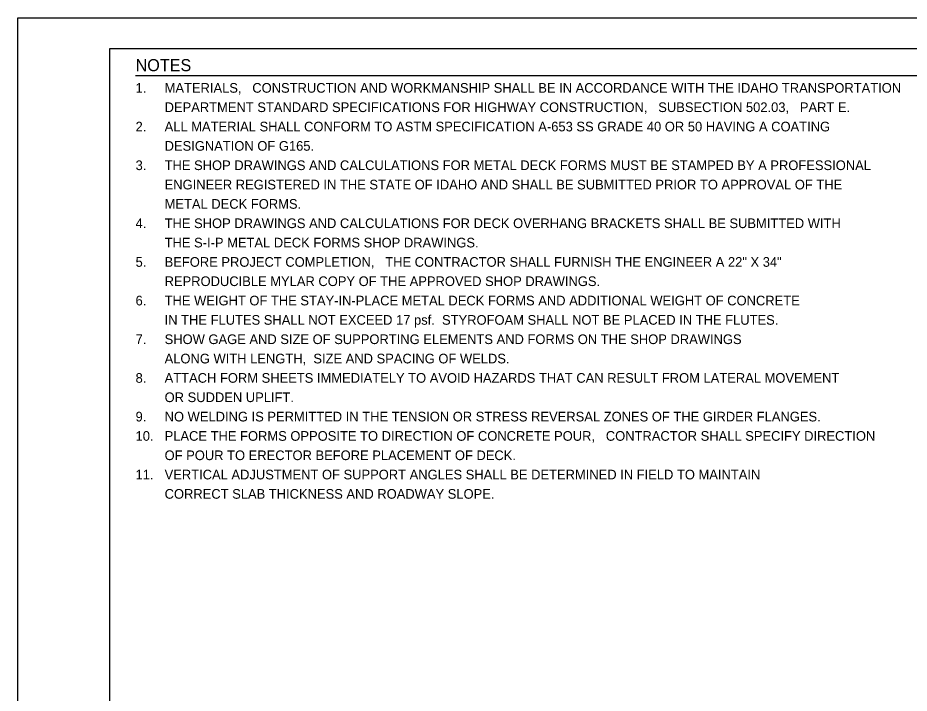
# Model space of a CAD drawing. Extents: x 0 to 34, y 0 to 23.5.
# Drawn here: x 0 to 14.51, y 11 to 22 of the extents above; entities that cross this region are included whole.
import ezdxf

# ---------------------------------------------------------------- set-up
doc = ezdxf.new("R2010")
doc.units = 0
for name, color, linetype in [('BORDER_ANNO_Cutsheet', 7, 'Continuous'), ('BRDG_ANNO_Anno-Sheet', 7, 'Continuous'), ('BRDG_ANNO_General-Notes', 7, 'Continuous')]:
    doc.layers.add(name, color=color, linetype=linetype)

msp = doc.modelspace()

# ---------------------------------------------------------------- linework, layer by layer
at = {"layer": 'BORDER_ANNO_Cutsheet'}
msp.add_lwpolyline([(0, 22), (34, 22), (34, 0), (0, 0)], close=True, dxfattribs=at)
at = {"layer": 'BRDG_ANNO_Anno-Sheet'}
msp.add_lwpolyline([(1.5, 21.5), (33.5, 21.5), (33.5, 0.5), (1.5, 0.5)], close=True, dxfattribs=at)
at = {"layer": 'BRDG_ANNO_General-Notes'}
msp.add_line((1.917, 21.061), (15.124, 21.061), dxfattribs=at)

# ---------------------------------------------------------------- texts
for s, height, p in [('NOTES', 0.1968, (1.917, 21.131)), ('1.', 0.1574, (1.917, 20.78)), ('MATERIALS,   CONSTRUCTION AND WORKMANSHIP SHALL BE IN ACCORDANCE WITH THE IDAHO TRANSPORTATION', 0.15746, (2.39, 20.78)), ('DEPARTMENT STANDARD SPECIFICATIONS FOR HIGHWAY CONSTRUCTION,   SUBSECTION 502.03,   PART E.', 0.15746, (2.39, 20.465)), ('2.', 0.1575, (1.917, 20.15)), ('ALL MATERIAL SHALL CONFORM TO ASTM SPECIFICATION A-653 SS GRADE 40 OR 50 HAVING A COATING', 0.15746, (2.39, 20.15)), ('DESIGNATION OF G165.', 0.15746, (2.39, 19.835)), ('3.', 0.1575, (1.917, 19.52)), ('THE SHOP DRAWINGS AND CALCULATIONS FOR METAL DECK FORMS MUST BE STAMPED BY A PROFESSIONAL', 0.15745, (2.39, 19.52)), ('ENGINEER REGISTERED IN THE STATE OF IDAHO AND SHALL BE SUBMITTED PRIOR TO APPROVAL OF THE', 0.15745, (2.39, 19.205)), ('METAL DECK FORMS.', 0.15745, (2.39, 18.89)), ('4.', 0.1575, (1.917, 18.575)), ('THE SHOP DRAWINGS AND CALCULATIONS FOR DECK OVERHANG BRACKETS SHALL BE SUBMITTED WITH', 0.15745, (2.39, 18.575)), ('THE S-I-P METAL DECK FORMS SHOP DRAWINGS.', 0.15745, (2.39, 18.26)), ('5.', 0.1575, (1.917, 17.945)), ('BEFORE PROJECT COMPLETION,   THE CONTRACTOR SHALL FURNISH THE ENGINEER A 22" X 34"', 0.15745, (2.39, 17.945)), ('REPRODUCIBLE MYLAR COPY OF THE APPROVED SHOP DRAWINGS.', 0.15745, (2.39, 17.631)), ('6.', 0.1575, (1.917, 17.316)), ('THE WEIGHT OF THE STAY-IN-PLACE METAL DECK FORMS AND ADDITIONAL WEIGHT OF CONCRETE', 0.15745, (2.39, 17.316)), ('IN THE FLUTES SHALL NOT EXCEED 17 psf.  STYROFOAM SHALL NOT BE PLACED IN THE FLUTES.', 0.15746, (2.39, 17.001)), ('7.', 0.1575, (1.917, 16.686)), ('SHOW GAGE AND SIZE OF SUPPORTING ELEMENTS AND FORMS ON THE SHOP DRAWINGS', 0.15745, (2.39, 16.686)), ('ALONG WITH LENGTH,  SIZE AND SPACING OF WELDS.', 0.15745, (2.39, 16.371)), ('8.', 0.1575, (1.917, 16.056)), ('ATTACH FORM SHEETS IMMEDIATELY TO AVOID HAZARDS THAT CAN RESULT FROM LATERAL MOVEMENT', 0.15745, (2.39, 16.056)), ('OR SUDDEN UPLIFT.', 0.15745, (2.39, 15.741)), ('9.', 0.1575, (1.917, 15.426)), ('NO WELDING IS PERMITTED IN THE TENSION OR STRESS REVERSAL ZONES OF THE GIRDER FLANGES.', 0.15746, (2.39, 15.426)), ('10.', 0.1575, (1.917, 15.111)), ('PLACE THE FORMS OPPOSITE TO DIRECTION OF CONCRETE POUR,   CONTRACTOR SHALL SPECIFY DIRECTION', 0.15746, (2.39, 15.111)), ('OF POUR TO ERECTOR BEFORE PLACEMENT OF DECK.', 0.15745, (2.39, 14.796)), ('11.', 0.1575, (1.917, 14.482)), ('VERTICAL ADJUSTMENT OF SUPPORT ANGLES SHALL BE DETERMINED IN FIELD TO MAINTAIN', 0.15745, (2.39, 14.482)), ('CORRECT SLAB THICKNESS AND ROADWAY SLOPE.', 0.15745, (2.39, 14.167))]:
    msp.add_text(s, height=height, dxfattribs=at).set_placement(p)

doc.saveas('drawing.dxf')
